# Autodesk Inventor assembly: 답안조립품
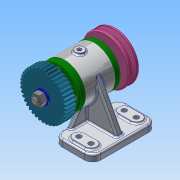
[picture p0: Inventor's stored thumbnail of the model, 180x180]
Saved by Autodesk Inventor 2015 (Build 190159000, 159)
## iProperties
Created: 2023-08
Part Number: 답안조립품
Document SubType Name: Assembly
Designer: 학생용
Author: 학생용
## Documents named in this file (12)
- C:\Users\학생용\Desktop\730806V1003\답안조립품.iam
- C:\Users\학생용\Desktop\730806V1003\1 본체.ipt
- C:\Users\학생용\Desktop\730806V1003\축.ipt
- C:\Users\학생용\Desktop\730806V1003\베어링 6204.ipt
- C:\Users\학생용\Desktop\730806V1003\커버.ipt
- C:\Users\학생용\Desktop\730806V1003\볼트 M4 x 12.ipt
- C:\Users\학생용\Desktop\730806V1003\오일실 20x35x8.ipt
- C:\Users\학생용\Desktop\730806V1003\키 5x5.ipt
- C:\Users\학생용\Desktop\730806V1003\V벨트풀리.ipt
- C:\Users\학생용\Desktop\730806V1003\스퍼기어.ipt
- C:\Users\학생용\Desktop\730806V1003\와셔 12x24.ipt
- C:\Users\학생용\Desktop\730806V1003\너트 M12x1.25.ipt
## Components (2 placed, 2 different names)
1. 1 본체:1
2. V벨트풀리:1 — 각도:3
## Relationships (1: Angle 1)
- 각도:3 [Angle]: V벨트풀리:1
